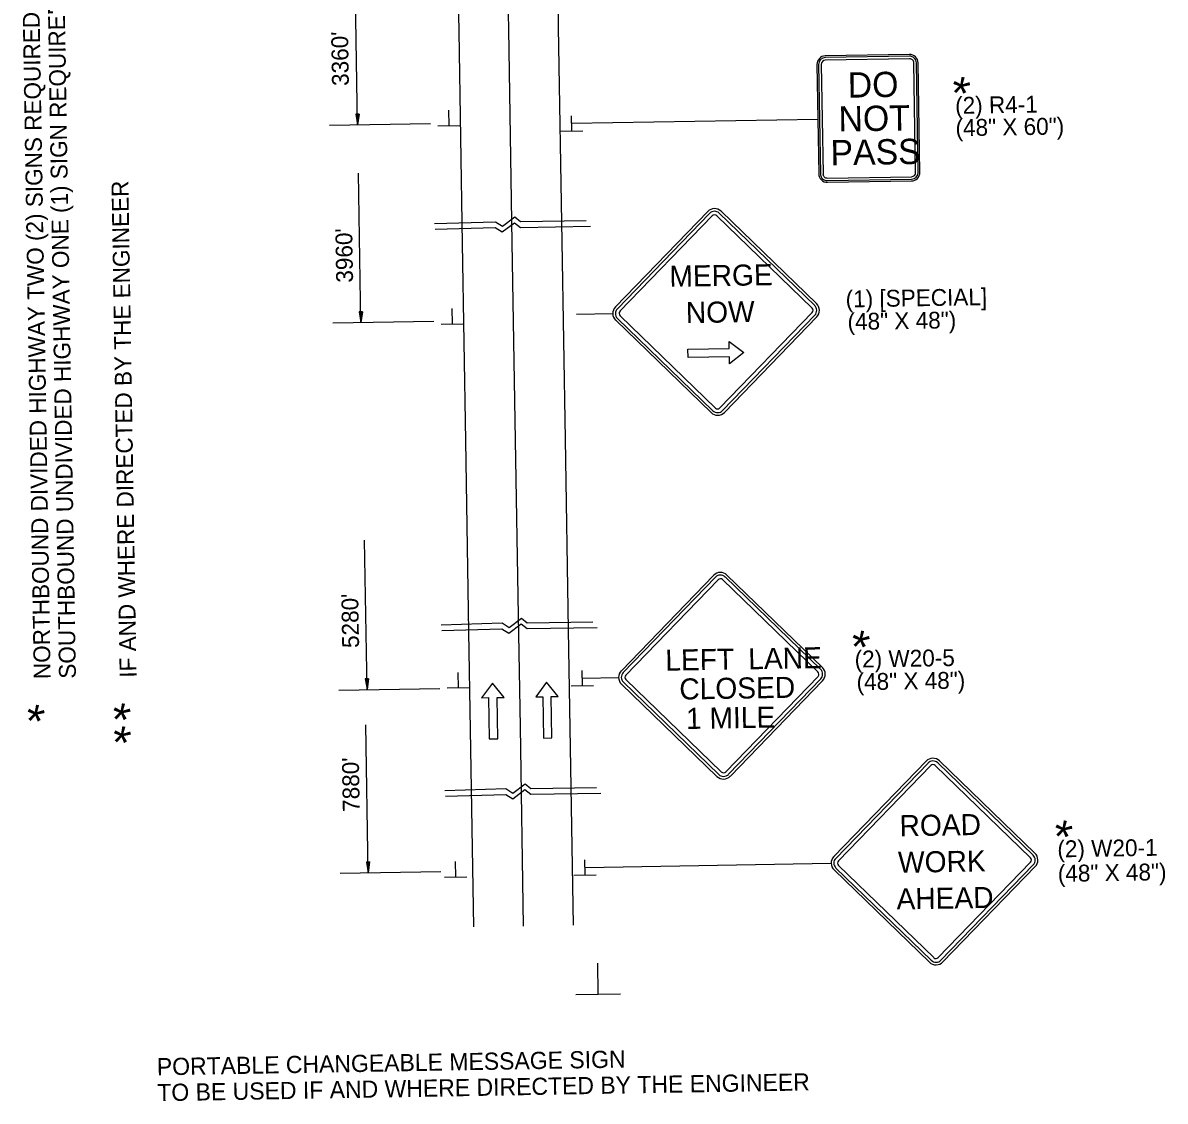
# Model space of a CAD drawing. Extents: x 1676063 to 1678026, y 228339 to 229904.
# Drawn here: x 1676133.6 to 1676540.3, y 228338.6 to 228722.5 of the extents above; entities that cross this region are included whole.
import ezdxf

# ---------------------------------------------------------------- set-up
doc = ezdxf.new("R2010")
doc.units = 0
for name, color, linetype in [('Default', 7, 'Continuous'), ('P_TC_Signs_Permanent', 7, 'Continuous'), ('P_TC_Signs_Temporary', 7, 'Continuous'), ('R_Annotation', 7, 'Continuous'), ('R_MOT', 7, 'Continuous')]:
    doc.layers.add(name, color=color, linetype=linetype)

msp = doc.modelspace()

# ---------------------------------------------------------------- linework, layer by layer
at = {"layer": 'Default'}
for p, q in [((1676288.9, 228719.41), (1676287.86, 228782.61)), ((1676306.63, 228720.17), (1676305.59, 228782.56)), ((1676324.35, 228720.93), (1676323.33, 228782.51)), ((1676252.81, 228686.18), (1676251.93, 228739.41)), ((1676290.15, 228644), (1676288.9, 228719.41)), ((1676307.88, 228644.3), (1676306.63, 228720.17)), ((1676325.61, 228644.59), (1676324.35, 228720.93)), ((1676253.32, 228690.02), (1676252.18, 228690)), ((1676252.18, 228690), (1676252.81, 228686.18)), ((1676252.27, 228690), (1676252.8, 228686.82)), ((1676252.37, 228690), (1676252.79, 228687.48)), ((1676252.47, 228690), (1676252.78, 228688.12)), ((1676252.56, 228690), (1676252.77, 228688.76)), ((1676252.66, 228690.01), (1676252.76, 228689.4)), ((1676252.84, 228690.01), (1676252.76, 228689.4)), ((1676252.94, 228690.01), (1676252.77, 228688.76)), ((1676253.04, 228690.01), (1676252.78, 228688.12)), ((1676253.13, 228690.01), (1676252.79, 228687.48)), ((1676253.23, 228690.01), (1676252.8, 228686.82)), ((1676253.32, 228690.02), (1676252.81, 228686.18)), ((1676285.41, 228685.91), (1676285.32, 228691.36)), ((1676242.83, 228686.02), (1676278.74, 228686.61)), ((1676289.38, 228685.86), (1676281.4, 228685.73)), ((1676329.07, 228684.01), (1676328.98, 228689.45)), ((1676333.04, 228683.96), (1676325.06, 228683.82)), ((1676253.98, 228615.81), (1676253.1, 228669.03)), ((1676291.32, 228573.63), (1676290.15, 228644)), ((1676309.05, 228573.92), (1676307.88, 228644.3)), ((1676326.78, 228574.22), (1676325.61, 228644.59)), ((1676286.58, 228615.29), (1676286.49, 228620.74)), ((1676254.49, 228619.64), (1676253.34, 228619.62)), ((1676253.34, 228619.62), (1676253.98, 228615.81)), ((1676253.44, 228619.63), (1676253.97, 228616.45)), ((1676253.54, 228619.63), (1676253.96, 228617.11)), ((1676253.63, 228619.63), (1676253.95, 228617.74)), ((1676253.73, 228619.63), (1676253.94, 228618.39)), ((1676253.83, 228619.63), (1676253.93, 228619.03)), ((1676254.01, 228619.63), (1676253.93, 228619.03)), ((1676254.1, 228619.64), (1676253.94, 228618.39)), ((1676254.2, 228619.64), (1676253.95, 228617.74)), ((1676254.3, 228619.64), (1676253.96, 228617.11)), ((1676254.4, 228619.64), (1676253.97, 228616.45)), ((1676254.49, 228619.64), (1676253.98, 228615.81)), ((1676244, 228615.64), (1676279.9, 228616.24)), ((1676290.55, 228615.24), (1676282.57, 228615.11)), ((1676292.45, 228505.69), (1676291.32, 228573.63)), ((1676310.08, 228511.53), (1676309.05, 228573.92)), ((1676327.91, 228506.33), (1676326.78, 228574.22)), ((1676256.15, 228485.1), (1676255.26, 228538.33)), ((1676310.74, 228471.83), (1676310.08, 228511.53)), ((1676293.03, 228470.76), (1676292.45, 228505.69)), ((1676328.48, 228471.4), (1676327.91, 228506.33)), ((1676288.74, 228485.76), (1676288.65, 228491.21)), ((1676332.86, 228486.49), (1676332.77, 228491.94)), ((1676256.66, 228488.94), (1676255.51, 228488.92)), ((1676255.51, 228488.92), (1676256.15, 228485.1)), ((1676255.61, 228488.92), (1676256.14, 228485.74)), ((1676255.7, 228488.92), (1676256.13, 228486.4)), ((1676255.8, 228488.92), (1676256.12, 228487.04)), ((1676255.9, 228488.92), (1676256.1, 228487.68)), ((1676255.99, 228488.93), (1676256.09, 228488.32)), ((1676256.17, 228488.93), (1676256.09, 228488.32)), ((1676256.27, 228488.93), (1676256.1, 228487.68)), ((1676256.37, 228488.93), (1676256.12, 228487.04)), ((1676256.46, 228488.93), (1676256.13, 228486.4)), ((1676256.56, 228488.93), (1676256.14, 228485.74)), ((1676256.66, 228488.94), (1676256.15, 228485.1)), ((1676336.83, 228486.44), (1676328.86, 228486.31)), ((1676246.16, 228484.94), (1676282.07, 228485.53)), ((1676292.71, 228485.71), (1676284.74, 228485.58)), ((1676256.55, 228419.91), (1676255.68, 228472.53)), ((1676294.19, 228400.62), (1676293.03, 228470.76)), ((1676311.92, 228400.91), (1676310.74, 228471.83)), ((1676329.65, 228401.21), (1676328.48, 228471.4)), ((1676257.06, 228423.74), (1676255.91, 228423.72)), ((1676255.91, 228423.72), (1676256.55, 228419.91)), ((1676256.01, 228423.72), (1676256.54, 228420.54)), ((1676256.1, 228423.72), (1676256.53, 228421.2)), ((1676256.2, 228423.72), (1676256.52, 228421.84)), ((1676256.3, 228423.73), (1676256.51, 228422.49)), ((1676256.39, 228423.73), (1676256.49, 228423.13)), ((1676256.57, 228423.73), (1676256.49, 228423.13)), ((1676256.67, 228423.73), (1676256.51, 228422.49)), ((1676256.77, 228423.73), (1676256.52, 228421.84)), ((1676256.87, 228423.74), (1676256.53, 228421.2)), ((1676256.96, 228423.74), (1676256.54, 228420.54)), ((1676257.06, 228423.74), (1676256.55, 228419.91)), ((1676287.74, 228418.42), (1676287.65, 228423.87)), ((1676333.82, 228419.08), (1676333.73, 228424.53)), ((1676246.56, 228419.74), (1676282.47, 228420.34)), ((1676291.71, 228418.37), (1676283.73, 228418.24)), ((1676337.79, 228419.03), (1676329.81, 228418.9)), ((1676338.48, 228376.82), (1676338.3, 228387.72)), ((1676346.42, 228376.72), (1676330.47, 228376.46))]:
    msp.add_line(p, q, dxfattribs=at)
for points in [[(1676280.16, 228651.02), (1676301.88, 228651.71), (1676304.37, 228650.1), (1676308.73, 228653.4), (1676310.8, 228651.73), (1676334.22, 228652.12)], [(1676280.38, 228648.99), (1676301.83, 228649.67), (1676304.32, 228648.06), (1676308.68, 228651.36), (1676310.75, 228649.69), (1676335.69, 228650.1)], [(1676282.52, 228508.15), (1676304.25, 228508.84), (1676306.74, 228507.23), (1676311.1, 228510.53), (1676313.17, 228508.86), (1676336.59, 228509.25)], [(1676282.75, 228506.12), (1676304.2, 228506.8), (1676306.69, 228505.19), (1676311.05, 228508.49), (1676313.12, 228506.82), (1676338.06, 228507.23)], [(1676283.84, 228449.15), (1676305.57, 228449.84), (1676308.06, 228448.23), (1676312.42, 228451.53), (1676314.49, 228449.86), (1676337.91, 228450.25)], [(1676284.07, 228447.12), (1676305.52, 228447.8), (1676308.01, 228446.19), (1676312.37, 228449.49), (1676314.44, 228447.82), (1676339.38, 228448.23)]]:
    msp.add_lwpolyline(points, dxfattribs=at)
at = {"layer": 'P_TC_Signs_Permanent'}
for p, q in [((1676449.3, 228711.23), (1676419.31, 228710.73)), ((1676449.31, 228710.63), (1676419.32, 228710.13)), ((1676416.36, 228707.68), (1676417.01, 228668.69)), ((1676416.96, 228707.69), (1676417.61, 228668.7)), ((1676417.86, 228707.71), (1676418.51, 228668.71)), ((1676449.33, 228709.73), (1676419.33, 228709.23)), ((1676451.5, 228669.26), (1676450.85, 228708.25)), ((1676452.4, 228669.27), (1676451.75, 228708.27)), ((1676453, 228669.28), (1676452.35, 228708.28)), ((1676420.03, 228667.24), (1676450.03, 228667.73)), ((1676420.04, 228666.34), (1676450.04, 228666.83)), ((1676420.05, 228665.74), (1676450.05, 228666.23))]:
    msp.add_line(p, q, dxfattribs=at)
for centre, radius, start, end in [((1676419.36, 228707.73), 3, 90.9497, 180.9497), ((1676419.36, 228707.73), 2.4, 90.9497, 180.9497), ((1676449.35, 228708.23), 3, 0.9497, 90.9497), ((1676449.35, 228708.23), 2.4, 0.9497, 90.9497), ((1676419.36, 228707.73), 1.5, 90.9497, 180.9497), ((1676449.35, 228708.23), 1.5, 0.9497, 90.9497), ((1676420, 228668.74), 3, 180.9497, 270.9497), ((1676420, 228668.74), 2.4, 180.9497, 270.9497), ((1676420, 228668.74), 1.5, 180.9497, 270.9497), ((1676450, 228669.23), 1.5, 270.9497, 0.9497), ((1676450, 228669.23), 2.4, 270.9497, 0.9497), ((1676450, 228669.23), 3, 270.9497, 0.9497)]:
    msp.add_arc(centre, radius, start, end, dxfattribs=at)
at = {"layer": 'P_TC_Signs_Temporary'}
for p, q in [((1676377.46, 228655.33), (1676344.61, 228621.37)), ((1676378.13, 228654.67), (1676345.28, 228620.71)), ((1676379.08, 228653.76), (1676346.22, 228619.8)), ((1676414.63, 228620.94), (1676380.67, 228653.79)), ((1676415.54, 228621.88), (1676381.58, 228654.73)), ((1676416.19, 228622.55), (1676382.23, 228655.4)), ((1676344.69, 228616.59), (1676378.65, 228583.74)), ((1676345.34, 228617.27), (1676379.3, 228584.41)), ((1676346.25, 228618.21), (1676380.21, 228585.36)), ((1676381.8, 228585.38), (1676414.65, 228619.34)), ((1676382.74, 228584.47), (1676415.6, 228618.43)), ((1676383.42, 228583.82), (1676416.27, 228617.78)), ((1676346.7, 228491.83), (1676379.55, 228525.79)), ((1676347.37, 228491.18), (1676380.22, 228525.14)), ((1676348.31, 228490.27), (1676381.17, 228524.23)), ((1676382.76, 228524.25), (1676416.72, 228491.4)), ((1676383.67, 228525.2), (1676417.63, 228492.34)), ((1676384.32, 228525.87), (1676418.28, 228493.02)), ((1676380.73, 228454.21), (1676346.77, 228487.06)), ((1676381.39, 228454.88), (1676347.43, 228487.73)), ((1676382.3, 228455.82), (1676348.34, 228488.68)), ((1676416.74, 228489.81), (1676383.89, 228455.85)), ((1676417.69, 228488.9), (1676384.83, 228454.94)), ((1676418.36, 228488.25), (1676385.51, 228454.29)), ((1676422.38, 228425.66), (1676455.23, 228459.62)), ((1676423.05, 228425.01), (1676455.9, 228458.97)), ((1676424, 228424.1), (1676456.85, 228458.06)), ((1676458.44, 228458.09), (1676492.4, 228425.23)), ((1676459.35, 228459.03), (1676493.31, 228426.18)), ((1676460, 228459.7), (1676493.96, 228426.85)), ((1676457.07, 228388.71), (1676423.11, 228421.57)), ((1676457.98, 228389.66), (1676424.02, 228422.51)), ((1676492.42, 228423.64), (1676459.57, 228389.68)), ((1676493.37, 228422.73), (1676460.52, 228388.77)), ((1676494.04, 228422.08), (1676461.19, 228388.12)), ((1676456.42, 228388.04), (1676422.46, 228420.89))]:
    msp.add_line(p, q, dxfattribs=at)
for centre, radius, start, end in [((1676379.88, 228652.98), 3.38, 45.9497, 135.9497), ((1676379.88, 228652.98), 2.44, 45.9497, 135.9497), ((1676379.88, 228652.98), 1.13, 45.9497, 135.9497), ((1676347.03, 228619.02), 3.38, 135.9497, 225.9497), ((1676347.03, 228619.02), 2.44, 135.9497, 225.9497), ((1676413.84, 228620.13), 1.12, 315.9497, 45.9497), ((1676413.84, 228620.13), 2.44, 315.9497, 45.9497), ((1676413.84, 228620.13), 3.38, 315.9497, 45.9497), ((1676347.03, 228619.02), 1.12, 135.9497, 225.9497), ((1676380.99, 228586.17), 2.44, 225.9497, 315.9497), ((1676380.99, 228586.17), 1.13, 225.9497, 315.9497), ((1676380.99, 228586.17), 3.38, 225.9497, 315.9497), ((1676381.97, 228523.44), 3.38, 45.9497, 135.9497), ((1676381.97, 228523.44), 2.44, 45.9497, 135.9497), ((1676381.97, 228523.44), 1.13, 45.9497, 135.9497), ((1676349.12, 228489.48), 3.38, 135.9497, 225.9497), ((1676349.12, 228489.48), 2.44, 135.9497, 225.9497), ((1676415.93, 228490.59), 1.12, 315.9497, 45.9497), ((1676415.93, 228490.59), 2.44, 315.9497, 45.9497), ((1676415.93, 228490.59), 3.38, 315.9497, 45.9497), ((1676349.12, 228489.48), 1.12, 135.9497, 225.9497), ((1676457.66, 228457.28), 3.38, 45.9497, 135.9497), ((1676457.66, 228457.28), 2.44, 45.9497, 135.9497), ((1676457.66, 228457.28), 1.13, 45.9497, 135.9497), ((1676383.08, 228456.63), 3.38, 225.9497, 315.9497), ((1676383.08, 228456.63), 2.44, 225.9497, 315.9497), ((1676383.08, 228456.63), 1.13, 225.9497, 315.9497), ((1676424.8, 228423.32), 3.38, 135.9497, 225.9497), ((1676491.62, 228424.43), 2.44, 315.9497, 45.9497), ((1676491.62, 228424.43), 3.38, 315.9497, 45.9497), ((1676424.8, 228423.32), 2.44, 135.9497, 225.9497), ((1676424.8, 228423.32), 1.12, 135.9497, 225.9497), ((1676491.62, 228424.43), 1.12, 315.9497, 45.9497), ((1676458.76, 228390.47), 2.44, 225.9497, 315.9497), ((1676458.76, 228390.47), 1.13, 225.9497, 315.9497), ((1676458.76, 228390.47), 3.38, 225.9497, 315.9497)]:
    msp.add_arc(centre, radius, start, end, dxfattribs=at)
at = {"layer": 'R_Annotation'}
for p, q in [((1676329.03, 228686.73), (1676416.68, 228688.18)), ((1676330.73, 228618.75), (1676343.66, 228618.96)), ((1676332.82, 228489.21), (1676345.75, 228489.43)), ((1676333.77, 228421.81), (1676421.43, 228423.26)), ((1676333.77, 228421.81), (1676421.43, 228423.26))]:
    msp.add_line(p, q, dxfattribs=at)
at = {"layer": 'R_MOT'}
for points in [[(1676385.07, 228609.04), (1676390.33, 228605.13), (1676385.2, 228601.04), (1676385.16, 228603.54), (1676370.45, 228603.3), (1676370.4, 228606.3), (1676385.11, 228606.54)], [(1676304.94, 228482.33), (1676300.85, 228487.45), (1676296.94, 228482.19), (1676299.44, 228482.24), (1676299.69, 228467.53), (1676302.69, 228467.58), (1676302.44, 228482.29)], [(1676324.2, 228482.65), (1676320.11, 228487.77), (1676316.2, 228482.51), (1676318.7, 228482.56), (1676318.96, 228467.85), (1676321.96, 228467.9), (1676321.7, 228482.61)]]:
    msp.add_lwpolyline(points, close=True, dxfattribs=at)

# ---------------------------------------------------------------- texts
at = {"layer": 'Default'}
for s, height, rotation, p in [("3360'", 6, 90.9497, (1676249.69, 228700.1)), ("3960'", 6, 90.9497, (1676251.18, 228630.04)), ("5280'", 6, 90.9497, (1676253.32, 228499.97)), ("7880'", 6, 90.9497, (1676253.55, 228441.62)), ('PORTABLE CHANGEABLE MESSAGE SIGN', 6.1199, 0.9497, (1676181.36, 228347.76)), ('TO BE USED IF AND WHERE DIRECTED BY THE ENGINEER', 6.1199, 0.9497, (1676181.52, 228338.54))]:
    msp.add_text(s, height=height, rotation=rotation, dxfattribs=at).set_placement(p)
at = {"layer": 'P_TC_Signs_Permanent'}
for s, rotation, p in [('DO', 0.9497, (1676427.39, 228695.86)), ('NOT', 0.9094, (1676424.1, 228683.81)), ('PASS', 0.9497, (1676421.25, 228671.76))]:
    msp.add_text(s, height=9, rotation=rotation, dxfattribs=at).set_placement(p)
at = {"layer": 'P_TC_Signs_Temporary'}
for s, p in [('MERGE', (1676363.88, 228628.51)), ('NOW', (1676369.72, 228615.58)), ('LEFT\u2002LANE', (1676362.41, 228491.83)), ('CLOSED', (1676367.41, 228481.54)), ('1 MILE', (1676369.79, 228471.07)), (' ROAD ', (1676443.04, 228432.83)), ('WORK', (1676445.28, 228419.85)), (' AHEAD ', (1676441.95, 228406.77))]:
    msp.add_text(s, height=7.5, rotation=0.9497, dxfattribs=at).set_placement(p)
at = {"layer": 'R_Annotation'}
for s, height, rotation, p in [('SOUTHBOUND UNDIVIDED HIGHWAY ONE (1) SIGN REQUIRED', 6, 90.9497, (1676152.5, 228489.04)), ('NORTHBOUND DIVIDED HIGHWAY TWO (2) SIGNS REQUIRED ', 6, 90.9497, (1676143.5, 228488.89)), ('*', 12, 135.9497, (1676476.13, 228704.3)), ('(2) R4-1', 6, 0.9497, (1676465.61, 228690.08)), ('(48" X 60")', 6, 0.9497, (1676465.74, 228682.14)), ('IF AND WHERE DIRECTED BY THE ENGINEER', 6, 90.9497, (1676174.09, 228489.4)), ('(1) [SPECIAL]', 6, 0.9497, (1676426.61, 228621.17)), ('(48" X 48")', 6, 0.9497, (1676427.29, 228613.13)), ('*', 12, 135.9497, (1676440.35, 228507.13)), ('(2) W20-5', 6, 0.9497, (1676429.82, 228492.92)), ('(48" X 48")', 6, 0.9497, (1676430.5, 228484.87)), ('*', 12, 135.9497, (1676146.57, 228480.76)), ('*', 12, 135.9497, (1676177.16, 228481.27)), ('*', 12, 135.9497, (1676177.29, 228473.09)), ('*', 12, 135.9497, (1676512.54, 228439.57)), ('(2) W20-1', 6, 0.9497, (1676502.01, 228425.36)), ('(48" X 48")', 6, 0.9497, (1676502.16, 228416.62))]:
    msp.add_text(s, height=height, rotation=rotation, dxfattribs=at).set_placement(p)

doc.saveas('drawing.dxf')
